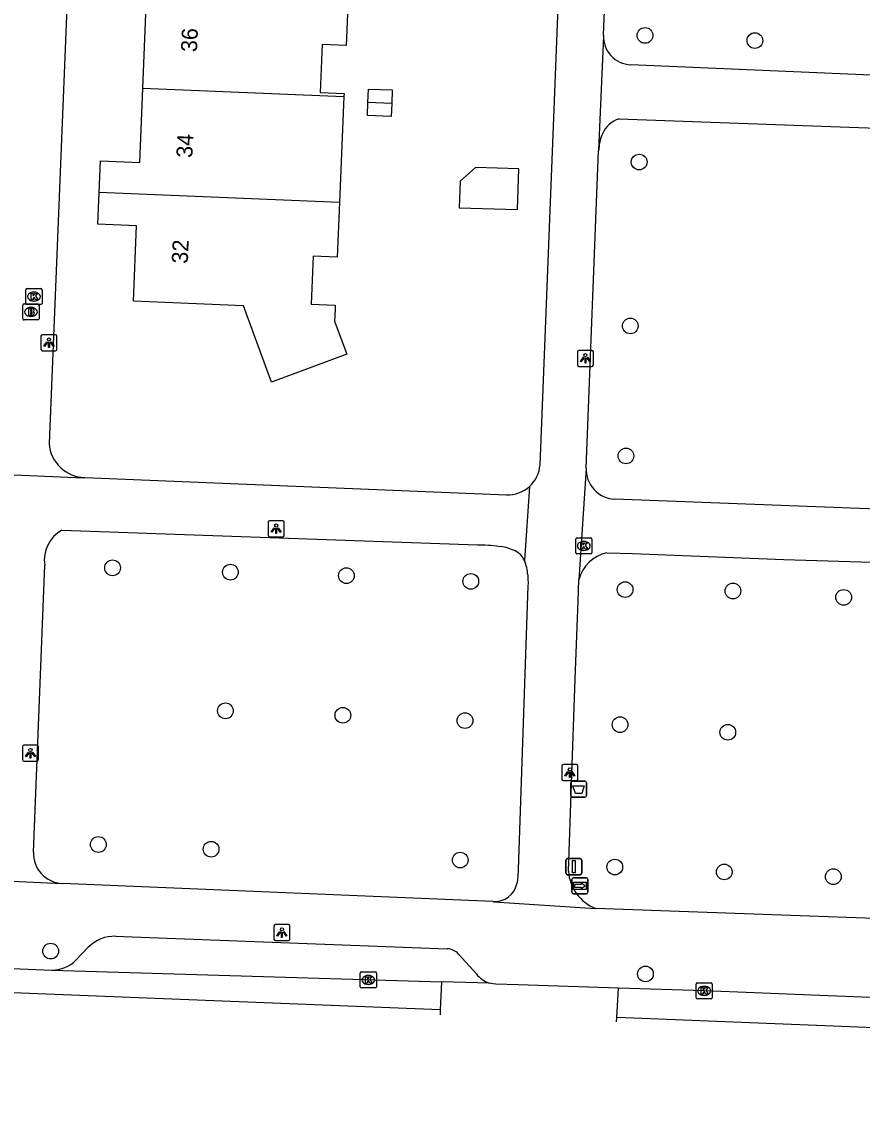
# Model space of a CAD drawing. Extents: x 160787 to 161428, y 386828 to 387483.
# Drawn here: x 161086.3 to 161138.7, y 386896.4 to 386964.7 of the extents above; entities that cross this region are included whole.
import ezdxf

# ---------------------------------------------------------------- set-up
doc = ezdxf.new("R2010")
doc.units = 0
for name, color, linetype in [('IMGEO_Afvalbak', 7, 'Continuous'), ('IMGEO_Boom', 7, 'Continuous'), ('IMGEO_Brandkraan', 7, 'Continuous'), ('IMGEO_Kolk', 7, 'Continuous'), ('IMGEO_Lichtpunt', 7, 'Continuous'), ('IMGEO_Pand', 7, 'Continuous'), ('IMGEO_Pand_nummerreeks', 7, 'Continuous'), ('IMGEO_Rijbaan_lokaal_gesloten', 7, 'Continuous'), ('IMGEO_Verkeersbordpaal', 7, 'Continuous'), ('IMGEO_Voetpad_open', 7, 'Continuous'), ('IMGEO_Wegwijzer', 7, 'Continuous')]:
    doc.layers.add(name, color=color, linetype=linetype)

msp = doc.modelspace()

# ---------------------------------------------------------------- linework, layer by layer
at = {"layer": 'IMGEO_Afvalbak'}
for p, q in [((161120.514, 386916.493), (161120.514, 386917.293)), ((161120.514, 386917.293), (161120.514, 386916.493)), ((161120.614, 386917.393), (161121.404, 386917.393)), ((161121.404, 386917.393), (161120.614, 386917.393)), ((161121.504, 386917.293), (161121.504, 386916.493)), ((161121.504, 386916.493), (161121.504, 386917.293)), ((161121.404, 386916.393), (161120.614, 386916.393)), ((161120.614, 386916.393), (161121.404, 386916.393))]:
    msp.add_line(p, q, dxfattribs=at)
msp.add_lwpolyline([(161120.657, 386917.107), (161121.361, 386917.107), (161121.212, 386916.637), (161120.806, 386916.637), (161120.657, 386917.107)], dxfattribs=at)
for centre, start, end in [((161120.614, 386917.293), 90, 180), ((161120.614, 386917.293), 90, 180), ((161121.404, 386917.293), 0, 90), ((161121.404, 386917.293), 360, 90), ((161120.614, 386916.493), 180, 270), ((161120.614, 386916.493), 180, 270), ((161121.404, 386916.493), 270, 0), ((161121.404, 386916.493), 270, 0)]:
    msp.add_arc(centre, 0.1, start, end, dxfattribs=at)
at = {"layer": 'IMGEO_Boom'}
for centre in [(161125.14, 386963.837), (161131.983, 386963.518), (161124.779, 386955.953), (161124.226, 386945.747), (161123.956, 386937.651), (161091.986, 386930.68), (161099.324, 386930.411), (161106.548, 386930.194), (161114.293, 386929.837), (161123.903, 386929.327), (161130.619, 386929.237), (161137.513, 386928.841), (161099.014, 386921.775), (161106.328, 386921.497), (161113.933, 386921.165), (161123.589, 386920.915), (161130.297, 386920.438), (161091.101, 386913.45), (161098.122, 386913.157), (161113.636, 386912.48), (161123.26, 386912.046), (161130.077, 386911.74), (161136.869, 386911.447), (161088.133, 386906.81), (161125.171, 386905.388)]:
    msp.add_circle(centre, 0.489, dxfattribs=at)
at = {"layer": 'IMGEO_Brandkraan'}
for p, q in [((161086.404, 386946.189), (161086.404, 386947.041)), ((161086.479, 386947.115), (161087.331, 386947.115)), ((161086.892, 386946.895), (161086.917, 386946.895)), ((161087.405, 386947.041), (161087.405, 386946.189)), ((161087.331, 386946.115), (161086.479, 386946.115)), ((161086.915, 386946.335), (161086.89, 386946.335))]:
    msp.add_line(p, q, dxfattribs=at)
for points in [[(161086.404, 386946.189), (161086.404, 386947.041)], [(161086.479, 386947.115), (161087.331, 386947.115)], [(161086.752, 386946.815), (161086.752, 386946.415), (161086.965, 386946.415)], [(161086.983, 386946.815), (161086.752, 386946.815)], [(161086.931, 386946.734), (161086.877, 386946.734), (161086.877, 386946.658)], [(161086.877, 386946.658), (161086.93, 386946.658)], [(161086.939, 386946.582), (161086.877, 386946.582), (161086.877, 386946.501)], [(161087.405, 386947.041), (161087.405, 386946.189)], [(161087.331, 386946.115), (161086.479, 386946.115)], [(161086.877, 386946.501), (161086.939, 386946.501)]]:
    msp.add_lwpolyline(points, dxfattribs=at)
for centre, radius, start, end in [((161086.481, 386947.039), 0.0765, 91.55205, 178.44795), ((161086.481, 386947.039), 0.0765, 91.55205, 178.44795), ((161086.932, 386946.696), 0.0379, 267.82845, 90.93552), ((161086.94, 386946.541), 0.0404, 269.87594, 90.50774), ((161086.987, 386946.67), 0.145, 59.4692, 91.53667), ((161087.012, 386946.717), 0.0922, 285.51372, 58.15012), ((161087.017, 386946.525), 0.105, 301.31148, 78.98903), ((161087.329, 386947.039), 0.0765, 1.55205, 88.44795), ((161087.329, 386947.039), 0.0765, 1.55205, 88.44795), ((161086.481, 386946.191), 0.0765, 181.55205, 268.44795), ((161086.481, 386946.191), 0.0765, 181.55205, 268.44795), ((161086.971, 386946.666), 0.251, 268.66757, 293.53466), ((161087.329, 386946.191), 0.0765, 271.55205, 358.44795), ((161087.329, 386946.191), 0.0765, 271.55205, 358.44795)]:
    msp.add_arc(centre, radius, start, end, dxfattribs=at)
for centre, major_axis, ratio, start_param, end_param in [((161086.891, 386946.615), (-0.387, 0.002), 0.722429, 4.712389, 7.853982), ((161086.916, 386946.615), (-0.39, 0.002), 0.717154, 1.570796, 4.712389)]:
    msp.add_ellipse(centre, major_axis=major_axis, ratio=ratio, start_param=start_param, end_param=end_param, dxfattribs=at)
at = {"layer": 'IMGEO_Kolk'}
for p, q in [((161086.591, 386947.146), (161086.591, 386947.998)), ((161086.666, 386948.072), (161087.518, 386948.072)), ((161087.592, 386947.998), (161087.592, 386947.146)), ((161087.102, 386947.292), (161087.077, 386947.292)), ((161087.079, 386947.852), (161087.104, 386947.852)), ((161087.518, 386947.072), (161086.666, 386947.072)), ((161120.828, 386931.619), (161120.828, 386932.471)), ((161120.903, 386932.545), (161121.755, 386932.545)), ((161121.316, 386932.325), (161121.341, 386932.325)), ((161121.829, 386932.471), (161121.829, 386931.619)), ((161121.755, 386931.545), (161120.903, 386931.545)), ((161121.339, 386931.765), (161121.314, 386931.765)), ((161107.412, 386904.589), (161107.412, 386905.441)), ((161107.487, 386905.515), (161108.339, 386905.515)), ((161107.9, 386905.295), (161107.925, 386905.295)), ((161108.413, 386905.441), (161108.413, 386904.589)), ((161108.339, 386904.515), (161107.487, 386904.515)), ((161107.923, 386904.735), (161107.898, 386904.735)), ((161128.328, 386903.909), (161128.328, 386904.761)), ((161128.403, 386904.835), (161129.255, 386904.835)), ((161128.816, 386904.615), (161128.841, 386904.615)), ((161129.329, 386904.761), (161129.329, 386903.909)), ((161129.255, 386903.835), (161128.403, 386903.835)), ((161128.839, 386904.055), (161128.814, 386904.055))]:
    msp.add_line(p, q, dxfattribs=at)
for points in [[(161086.591, 386947.146), (161086.591, 386947.998)], [(161086.666, 386948.072), (161087.518, 386948.072)], [(161087.592, 386947.998), (161087.592, 386947.146)], [(161086.912, 386947.772), (161087.035, 386947.772), (161087.035, 386947.621), (161087.165, 386947.772), (161087.329, 386947.772), (161087.183, 386947.621), (161087.336, 386947.372), (161087.184, 386947.372), (161087.099, 386947.536), (161087.035, 386947.469), (161087.035, 386947.372), (161086.912, 386947.372), (161086.912, 386947.772)], [(161087.518, 386947.072), (161086.666, 386947.072)], [(161120.828, 386931.619), (161120.828, 386932.471)], [(161120.903, 386932.545), (161121.755, 386932.545)], [(161121.149, 386932.245), (161121.272, 386932.245), (161121.272, 386932.094), (161121.402, 386932.245), (161121.566, 386932.245), (161121.42, 386932.094), (161121.573, 386931.845), (161121.421, 386931.845), (161121.336, 386932.009), (161121.272, 386931.942), (161121.272, 386931.845), (161121.149, 386931.845), (161121.149, 386932.245)], [(161121.829, 386932.471), (161121.829, 386931.619)], [(161121.755, 386931.545), (161120.903, 386931.545)], [(161107.412, 386904.589), (161107.412, 386905.441)], [(161107.487, 386905.515), (161108.339, 386905.515)], [(161107.733, 386905.215), (161107.856, 386905.215), (161107.856, 386905.064), (161107.986, 386905.215), (161108.15, 386905.215), (161108.004, 386905.064), (161108.157, 386904.815), (161108.005, 386904.815), (161107.92, 386904.979), (161107.856, 386904.912), (161107.856, 386904.815), (161107.733, 386904.815), (161107.733, 386905.215)], [(161108.413, 386905.441), (161108.413, 386904.589)], [(161108.339, 386904.515), (161107.487, 386904.515)], [(161128.328, 386903.909), (161128.328, 386904.761)], [(161128.403, 386904.835), (161129.255, 386904.835)], [(161128.649, 386904.535), (161128.772, 386904.535), (161128.772, 386904.384), (161128.902, 386904.535), (161129.066, 386904.535), (161128.92, 386904.384), (161129.073, 386904.135), (161128.921, 386904.135), (161128.836, 386904.299), (161128.772, 386904.232), (161128.772, 386904.135), (161128.649, 386904.135), (161128.649, 386904.535)], [(161129.329, 386904.761), (161129.329, 386903.909)], [(161129.255, 386903.835), (161128.403, 386903.835)]]:
    msp.add_lwpolyline(points, dxfattribs=at)
for centre, start, end in [((161086.668, 386947.996), 91.55205, 178.44795), ((161086.668, 386947.996), 91.55205, 178.44795), ((161087.516, 386947.996), 1.55205, 88.44795), ((161087.516, 386947.996), 1.55205, 88.44795), ((161086.668, 386947.148), 181.55205, 268.44795), ((161086.668, 386947.148), 181.55205, 268.44795), ((161087.516, 386947.148), 271.55205, 358.44795), ((161087.516, 386947.148), 271.55205, 358.44795), ((161120.905, 386932.469), 91.55205, 178.44795), ((161120.905, 386932.469), 91.55205, 178.44795), ((161121.753, 386932.469), 1.55205, 88.44795), ((161121.753, 386932.469), 1.55205, 88.44795), ((161120.905, 386931.621), 181.55205, 268.44795), ((161120.905, 386931.621), 181.55205, 268.44795), ((161121.753, 386931.621), 271.55205, 358.44795), ((161121.753, 386931.621), 271.55205, 358.44795), ((161107.489, 386905.439), 91.55205, 178.44795), ((161107.489, 386905.439), 91.55205, 178.44795), ((161108.337, 386905.439), 1.55205, 88.44795), ((161108.337, 386905.439), 1.55205, 88.44795), ((161107.489, 386904.591), 181.55205, 268.44795), ((161107.489, 386904.591), 181.55205, 268.44795), ((161108.337, 386904.591), 271.55205, 358.44795), ((161108.337, 386904.591), 271.55205, 358.44795), ((161128.405, 386904.759), 91.55205, 178.44795), ((161128.405, 386904.759), 91.55205, 178.44795), ((161129.253, 386904.759), 1.55205, 88.44795), ((161129.253, 386904.759), 1.55205, 88.44795), ((161128.405, 386903.911), 181.55205, 268.44795), ((161128.405, 386903.911), 181.55205, 268.44795), ((161129.253, 386903.911), 271.55205, 358.44795), ((161129.253, 386903.911), 271.55205, 358.44795)]:
    msp.add_arc(centre, 0.0765, start, end, dxfattribs=at)
for centre, major_axis, ratio, start_param, end_param in [((161087.078, 386947.572), (-0.387, 0.002), 0.722429, 4.712389, 7.853982), ((161087.103, 386947.572), (-0.39, 0.002), 0.717154, 1.570796, 4.712389), ((161121.315, 386932.045), (-0.387, 0.002), 0.722429, 4.712389, 7.853982), ((161121.34, 386932.045), (-0.39, 0.002), 0.717154, 1.570796, 4.712389), ((161107.899, 386905.015), (-0.387, 0.002), 0.722429, 4.712389, 7.853982), ((161107.924, 386905.015), (-0.39, 0.002), 0.717154, 1.570796, 4.712389), ((161128.815, 386904.335), (-0.387, 0.002), 0.722429, 4.712389, 7.853982), ((161128.84, 386904.335), (-0.39, 0.002), 0.717154, 1.570796, 4.712389)]:
    msp.add_ellipse(centre, major_axis=major_axis, ratio=ratio, start_param=start_param, end_param=end_param, dxfattribs=at)
at = {"layer": 'IMGEO_Lichtpunt'}
for p, q in [((161088.431, 386945.196), (161087.623, 386945.196)), ((161088.431, 386945.196), (161087.623, 386945.196)), ((161087.529, 386945.101), (161087.529, 386944.294)), ((161087.529, 386945.101), (161087.529, 386944.294)), ((161088.525, 386944.294), (161088.525, 386945.101)), ((161088.525, 386944.294), (161088.525, 386945.101)), ((161087.623, 386944.2), (161088.431, 386944.2)), ((161087.623, 386944.2), (161088.431, 386944.2)), ((161120.931, 386944.129), (161120.931, 386943.322)), ((161120.931, 386944.129), (161120.931, 386943.322)), ((161121.833, 386944.224), (161121.025, 386944.224)), ((161121.833, 386944.224), (161121.025, 386944.224)), ((161121.927, 386943.322), (161121.927, 386944.129)), ((161121.927, 386943.322), (161121.927, 386944.129)), ((161121.025, 386943.228), (161121.833, 386943.228)), ((161121.025, 386943.228), (161121.833, 386943.228)), ((161102.581, 386933.613), (161101.773, 386933.613)), ((161102.581, 386933.613), (161101.773, 386933.613)), ((161101.679, 386933.518), (161101.679, 386932.711)), ((161101.679, 386933.518), (161101.679, 386932.711)), ((161102.675, 386932.711), (161102.675, 386933.518)), ((161102.675, 386932.711), (161102.675, 386933.518)), ((161101.773, 386932.617), (161102.581, 386932.617)), ((161101.773, 386932.617), (161102.581, 386932.617)), ((161086.373, 386919.542), (161086.373, 386918.735)), ((161086.373, 386919.542), (161086.373, 386918.735)), ((161087.275, 386919.637), (161086.467, 386919.637)), ((161087.275, 386919.637), (161086.467, 386919.637)), ((161087.369, 386918.735), (161087.369, 386919.542)), ((161087.369, 386918.735), (161087.369, 386919.542)), ((161086.467, 386918.641), (161087.275, 386918.641)), ((161086.467, 386918.641), (161087.275, 386918.641)), ((161119.966, 386918.329), (161119.966, 386917.522)), ((161119.966, 386918.329), (161119.966, 386917.522)), ((161120.868, 386918.424), (161120.06, 386918.424)), ((161120.868, 386918.424), (161120.06, 386918.424)), ((161120.962, 386917.522), (161120.962, 386918.329)), ((161120.962, 386917.522), (161120.962, 386918.329)), ((161120.06, 386917.428), (161120.868, 386917.428)), ((161120.06, 386917.428), (161120.868, 386917.428)), ((161102.034, 386908.366), (161102.034, 386907.559)), ((161102.034, 386908.366), (161102.034, 386907.559)), ((161102.936, 386908.461), (161102.128, 386908.461)), ((161102.936, 386908.461), (161102.128, 386908.461)), ((161103.03, 386907.559), (161103.03, 386908.366)), ((161103.03, 386907.559), (161103.03, 386908.366)), ((161102.128, 386907.465), (161102.936, 386907.465)), ((161102.128, 386907.465), (161102.936, 386907.465))]:
    msp.add_line(p, q, dxfattribs=at)
for points in [[(161087.903, 386944.765), (161087.942, 386944.737), (161087.754, 386944.475), (161087.716, 386944.502), (161087.903, 386944.765)], [(161088.005, 386944.717), (161088.052, 386944.717), (161088.052, 386944.395), (161088.005, 386944.395), (161088.005, 386944.717)], [(161088.115, 386944.737), (161088.153, 386944.764), (161088.34, 386944.502), (161088.301, 386944.474), (161088.115, 386944.737)], [(161121.305, 386943.793), (161121.344, 386943.765), (161121.156, 386943.503), (161121.118, 386943.53), (161121.305, 386943.793)], [(161121.407, 386943.745), (161121.454, 386943.745), (161121.454, 386943.423), (161121.407, 386943.423), (161121.407, 386943.745)], [(161121.517, 386943.765), (161121.555, 386943.792), (161121.742, 386943.53), (161121.703, 386943.502), (161121.517, 386943.765)], [(161102.053, 386933.182), (161102.092, 386933.154), (161101.904, 386932.892), (161101.866, 386932.919), (161102.053, 386933.182)], [(161102.155, 386933.134), (161102.202, 386933.134), (161102.202, 386932.812), (161102.155, 386932.812), (161102.155, 386933.134)], [(161102.265, 386933.154), (161102.303, 386933.181), (161102.49, 386932.919), (161102.451, 386932.891), (161102.265, 386933.154)], [(161086.747, 386919.206), (161086.786, 386919.178), (161086.598, 386918.916), (161086.56, 386918.943), (161086.747, 386919.206)], [(161086.849, 386919.158), (161086.896, 386919.158), (161086.896, 386918.836), (161086.849, 386918.836), (161086.849, 386919.158)], [(161086.959, 386919.178), (161086.997, 386919.205), (161087.184, 386918.943), (161087.145, 386918.915), (161086.959, 386919.178)], [(161120.34, 386917.993), (161120.379, 386917.965), (161120.191, 386917.703), (161120.153, 386917.73), (161120.34, 386917.993)], [(161120.442, 386917.945), (161120.489, 386917.945), (161120.489, 386917.623), (161120.442, 386917.623), (161120.442, 386917.945)], [(161120.552, 386917.965), (161120.59, 386917.992), (161120.777, 386917.73), (161120.738, 386917.702), (161120.552, 386917.965)], [(161102.408, 386908.03), (161102.447, 386908.002), (161102.259, 386907.74), (161102.221, 386907.767), (161102.408, 386908.03)], [(161102.51, 386907.982), (161102.557, 386907.982), (161102.557, 386907.66), (161102.51, 386907.66), (161102.51, 386907.982)], [(161102.62, 386908.002), (161102.658, 386908.029), (161102.845, 386907.767), (161102.806, 386907.739), (161102.62, 386908.002)]]:
    msp.add_lwpolyline(points, dxfattribs=at)
for centre in [(161088.028, 386944.899), (161121.43, 386943.927), (161102.178, 386933.316), (161086.872, 386919.34), (161120.465, 386918.127), (161102.533, 386908.164)]:
    msp.add_circle(centre, 0.0994, dxfattribs=at)
for centre, start, end in [((161087.623, 386945.101), 90, 180), ((161087.623, 386945.101), 90, 180), ((161088.431, 386945.101), 0, 90), ((161088.431, 386945.101), 0, 90), ((161087.623, 386944.294), 180, 270), ((161087.623, 386944.294), 180, 270), ((161088.431, 386944.294), 270, 0), ((161088.431, 386944.294), 270, 360), ((161121.025, 386944.129), 90, 180), ((161121.025, 386944.129), 90, 180), ((161121.833, 386944.129), 0, 90), ((161121.833, 386944.129), 0, 90), ((161121.025, 386943.322), 180, 270), ((161121.025, 386943.322), 180, 270), ((161121.833, 386943.322), 270, 0), ((161121.833, 386943.322), 270, 360), ((161101.773, 386933.518), 90, 180), ((161101.773, 386933.518), 90, 180), ((161102.581, 386933.518), 0, 90), ((161102.581, 386933.518), 0, 90), ((161101.773, 386932.711), 180, 270), ((161101.773, 386932.711), 180, 270), ((161102.581, 386932.711), 270, 0), ((161102.581, 386932.711), 270, 360), ((161086.467, 386919.542), 90, 180), ((161086.467, 386919.542), 90, 180), ((161087.275, 386919.542), 0, 90), ((161087.275, 386919.542), 0, 90), ((161086.467, 386918.735), 180, 270), ((161086.467, 386918.735), 180, 270), ((161087.275, 386918.735), 270, 0), ((161087.275, 386918.735), 270, 360), ((161120.06, 386918.329), 90, 180), ((161120.06, 386918.329), 90, 180), ((161120.868, 386918.329), 0, 90), ((161120.868, 386918.329), 0, 90), ((161120.06, 386917.522), 180, 270), ((161120.06, 386917.522), 180, 270), ((161120.868, 386917.522), 270, 0), ((161120.868, 386917.522), 270, 360), ((161102.128, 386908.366), 90, 180), ((161102.128, 386908.366), 90, 180), ((161102.936, 386908.366), 0, 90), ((161102.936, 386908.366), 0, 90), ((161102.128, 386907.559), 180, 270), ((161102.128, 386907.559), 180, 270), ((161102.936, 386907.559), 270, 0), ((161102.936, 386907.559), 270, 360)]:
    msp.add_arc(centre, 0.0946, start, end, dxfattribs=at)
at = {"layer": 'IMGEO_Pand'}
for points in [[(161093.874, 386960.552), (161094.065, 386965.19), (161091.639, 386965.29), (161091.722, 386967.298)], [(161106.672, 386966.677), (161106.528, 386963.209), (161105.029, 386963.271), (161104.905, 386960.274), (161106.403, 386960.212), (161106.396, 386960.032)], [(161091.153, 386954.048), (161091.234, 386956.018), (161093.683, 386955.917), (161093.874, 386960.552)], [(161093.874, 386960.552), (161106.396, 386960.032)], [(161107.889, 386959.656), (161107.918, 386960.491), (161109.396, 386960.439), (161109.367, 386959.604)], [(161106.396, 386960.032), (161106.121, 386953.426)], [(161109.367, 386959.604), (161109.339, 386958.79), (161107.86, 386958.842), (161107.889, 386959.656)], [(161109.367, 386959.604), (161107.889, 386959.656)], [(161114.588, 386955.605), (161113.625, 386954.759), (161113.574, 386953.101), (161117.205, 386952.988), (161117.284, 386955.521), (161114.588, 386955.605)], [(161106.121, 386953.426), (161105.98, 386950.035), (161104.481, 386950.097), (161104.357, 386947.099), (161105.856, 386947.038), (161105.845, 386946.768), (161105.815, 386946.036), (161106.574, 386943.978), (161101.892, 386942.251), (161100.139, 386947.003), (161093.282, 386947.285), (161093.476, 386951.978), (161091.071, 386952.077), (161091.153, 386954.048)], [(161106.121, 386953.426), (161091.153, 386954.048)]]:
    msp.add_lwpolyline(points, dxfattribs=at)
at = {"layer": 'IMGEO_Rijbaan_lokaal_gesloten'}
for points in [[(161112.394, 386903.16), (160997.039, 386907.744)], [(161082.721, 386905.854), (161088.199, 386905.631)], [(161088.199, 386905.631), (161112.475, 386904.906)], [(161112.475, 386904.906), (161112.394, 386903.16)], [(161115.449, 386904.817), (161112.475, 386904.906)], [(161123.496, 386904.504), (161117.234, 386904.703), (161115.862, 386904.747), (161115.657, 386904.782), (161115.449, 386904.817)], [(161123.39, 386902.685), (161123.496, 386904.504)], [(161151.67, 386903.416), (161135.502, 386904.066), (161131.97, 386904.208), (161128.825, 386904.334), (161123.496, 386904.504)], [(161112.394, 386903.16), (161112.38, 386902.848)], [(161123.374, 386902.409), (161123.39, 386902.685)], [(161280.349, 386896.413), (161248.174, 386897.682), (161123.39, 386902.685)]]:
    msp.add_lwpolyline(points, dxfattribs=at)
at = {"layer": 'IMGEO_Verkeersbordpaal'}
for p, q in [((161120.216, 386911.67), (161120.216, 386912.47)), ((161120.216, 386912.47), (161120.216, 386911.67)), ((161120.316, 386912.57), (161121.106, 386912.57)), ((161121.106, 386912.57), (161120.316, 386912.57)), ((161121.206, 386912.47), (161121.206, 386911.67)), ((161121.206, 386911.67), (161121.206, 386912.47)), ((161121.106, 386911.57), (161120.316, 386911.57)), ((161120.316, 386911.57), (161121.106, 386911.57))]:
    msp.add_line(p, q, dxfattribs=at)
msp.add_lwpolyline([(161120.636, 386912.445), (161120.786, 386912.445), (161120.786, 386911.695), (161120.636, 386911.695), (161120.636, 386912.445)], dxfattribs=at)
for centre, start, end in [((161120.316, 386912.47), 90, 180), ((161120.316, 386912.47), 90, 180), ((161121.106, 386912.47), 0, 90), ((161121.106, 386912.47), 360, 90), ((161120.316, 386911.67), 180, 270), ((161120.316, 386911.67), 180, 270), ((161121.106, 386911.67), 270, 0), ((161121.106, 386911.67), 270, 0)]:
    msp.add_arc(centre, 0.1, start, end, dxfattribs=at)
at = {"layer": 'IMGEO_Voetpad_open'}
for points in [[(161122.553, 386963.852), (161124.044, 387000), (161126.838, 387069.748)], [(161092.128, 387039.776), (161090.524, 387000), (161090.045, 386988.116), (161088.04, 386938.415)], [(161118.604, 386937.102), (161119.475, 386959.244), (161121.076, 387000), (161122.596, 387038.706)], [(161122.553, 386963.852), (161122.549, 386963.816), (161122.251, 386956.693), (161122.253, 386956.657)], [(161145.968, 386961.082), (161124.256, 386962.014)], [(161123.522, 386958.645), (161144.741, 386957.868), (161145.293, 386957.851), (161145.823, 386957.811)], [(161121.473, 386936.897), (161122.253, 386956.657)], [(161082.88, 386936.613), (161082.967, 386936.595), (161090.15, 386936.295), (161090.255, 386936.31)], [(161090.255, 386936.31), (161116.527, 386935.233)], [(161121.473, 386936.897), (161121.017, 386929.934)], [(161117.946, 386935.745), (161117.632, 386931.131)], [(161145.036, 386934.128), (161123.268, 386934.957)], [(161088.821, 386933.031), (161114.707, 386932.115), (161114.937, 386932.11), (161115.17, 386932.104), (161115.406, 386932.094), (161115.54, 386932.085), (161115.897, 386932.052), (161116.146, 386932.017)], [(161122.772, 386931.616), (161124.372, 386931.578), (161133.792, 386931.194), (161144.763, 386930.859)], [(161087.064, 386912.968), (161087.76, 386930.841)], [(161117.841, 386930.237), (161117.855, 386929.983), (161117.858, 386929.72), (161117.855, 386929.563), (161117.237, 386911.903), (161117.227, 386911.479), (161117.177, 386911.067)], [(161120.37, 386911.783), (161120.564, 386917.225), (161120.797, 386923.755), (161120.97, 386928.628), (161121.017, 386929.934)], [(161081.696, 386911.369), (161081.725, 386911.364), (161088.828, 386911.021), (161088.857, 386911.024)], [(161115.665, 386909.903), (161088.857, 386911.024)], [(161115.665, 386909.903), (161115.728, 386909.89), (161122.06, 386909.472)], [(161144.206, 386908.675), (161143.967, 386908.672), (161143.729, 386908.68), (161143.492, 386908.694), (161122.06, 386909.472)], [(161092.189, 386907.732), (161092.659, 386907.712), (161112.831, 386906.951)], [(161089.701, 386906.247), (161090.475, 386907.047)], [(161113.536, 386906.622), (161114.641, 386905.399)]]:
    msp.add_lwpolyline(points, dxfattribs=at)
for centre, radius, start, end in [((161124.323, 386963.784), 1.772, 177.81019, 267.82314), ((161124.039, 386957.033), 1.693, 107.7634, 156.49151), ((161125.375, 386956.516), 3.125, 157.58306, 177.41706), ((161090.29, 386938.565), 2.255, 183.81878, 269.09843), ((161116.611, 386937.23), 1.997, 311.94992, 356.31323), ((161123.339, 386936.823), 1.867, 177.72583, 267.82773), ((161116.609, 386937.229), 1.997, 267.65398, 312.02668), ((161089.898, 386931.157), 2.161, 119.89315, 188.4088), ((161115.645, 386928.808), 3.247, 64.19524, 81.13245), ((161116.527, 386930.651), 1.205, 23.48422, 63.78328), ((161123.248, 386929.363), 2.303, 101.928, 165.63851), ((161115.327, 386930.121), 2.517, 2.64813, 23.66854), ((161088.935, 386912.895), 1.873, 177.76397, 267.60827), ((161123.063, 386911.979), 2.7, 184.16245, 248.19245), ((161115.786, 386911.309), 1.412, 265.06653, 350.11459), ((161092.09, 386905.492), 2.242, 87.47339, 136.09484), ((161112.795, 386905.954), 0.998, 42.03488, 87.93134), ((161088.209, 386907.746), 2.115, 269.73566, 314.86335), ((161115.915, 386906.316), 1.57, 215.74912, 252.72069)]:
    msp.add_arc(centre, radius, start, end, dxfattribs=at)
at = {"layer": 'IMGEO_Wegwijzer'}
for p, q in [((161120.591, 386910.478), (161120.591, 386911.278)), ((161120.591, 386911.278), (161120.591, 386910.478)), ((161120.691, 386911.378), (161121.481, 386911.378)), ((161121.481, 386911.378), (161120.691, 386911.378)), ((161121.581, 386911.278), (161121.581, 386910.478)), ((161121.581, 386910.478), (161121.581, 386911.278)), ((161121.481, 386910.378), (161120.691, 386910.378)), ((161120.691, 386910.378), (161121.481, 386910.378))]:
    msp.add_line(p, q, dxfattribs=at)
for points in [[(161120.692, 386911.11), (161121.48, 386911.11), (161121.48, 386910.646), (161120.692, 386910.646), (161120.692, 386911.11)], [(161120.757, 386910.962), (161120.757, 386910.878), (161120.757, 386910.794), (161121.168, 386910.794), (161121.168, 386910.711), (161121.415, 386910.878), (161121.168, 386911.045), (161121.168, 386910.962), (161120.757, 386910.962)]]:
    msp.add_lwpolyline(points, dxfattribs=at)
for centre, start, end in [((161120.691, 386911.278), 90, 180), ((161120.691, 386911.278), 90, 180), ((161121.481, 386911.278), 0, 90), ((161121.481, 386911.278), 360, 90), ((161120.691, 386910.478), 180, 270), ((161120.691, 386910.478), 180, 270), ((161121.481, 386910.478), 270, 0), ((161121.481, 386910.478), 270, 0)]:
    msp.add_arc(centre, 0.1, start, end, dxfattribs=at)

# ---------------------------------------------------------------- texts
at = {"layer": 'IMGEO_Pand_nummerreeks'}
for s, rotation, p in [('36', 87.50211, (161097.241, 386962.787)), ('34', 87.50085, (161096.954, 386956.199)), ('32', 87.50211, (161096.666, 386949.608))]:
    msp.add_text(s, height=1, rotation=rotation, dxfattribs=at).set_placement(p)

doc.saveas('drawing.dxf')
